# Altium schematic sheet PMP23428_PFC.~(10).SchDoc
size 431 x 279 mm; Date: Not shown in title block; ApprovedBy: Not shown in title block; CheckedBy: Not shown in title block; Author: Not shown in title block; CompanyName: Not shown in title block; Engineer: Not shown in title block; Organization: Not shown in title block; Address1: Not shown in title block; Address2: Not shown in title block; Address3: Not shown in title block; Address4: Not shown in title block; DocumentNumber: 1; Revision: Use project parameter SCH_Rev; SheetNumber: 1; SheetTotal: 3; PageSetup: Record=PageOptions¦CenterHorizontal=True¦CenterVertical=True¦PrintScale=1.00¦XCorrection=1.00¦YCorrection=1.00¦PrintKind=0¦BorderSize=5000000¦LeftOffset=0¦BottomOffset=0¦Orientation=2¦PaperLength=1000¦PaperWidth=1000¦Scale=100¦PaperSource=15¦PrintQuality=600¦MediaType=1¦DitherType=10¦PaperKind=Letter¦PrintScaleMode=1
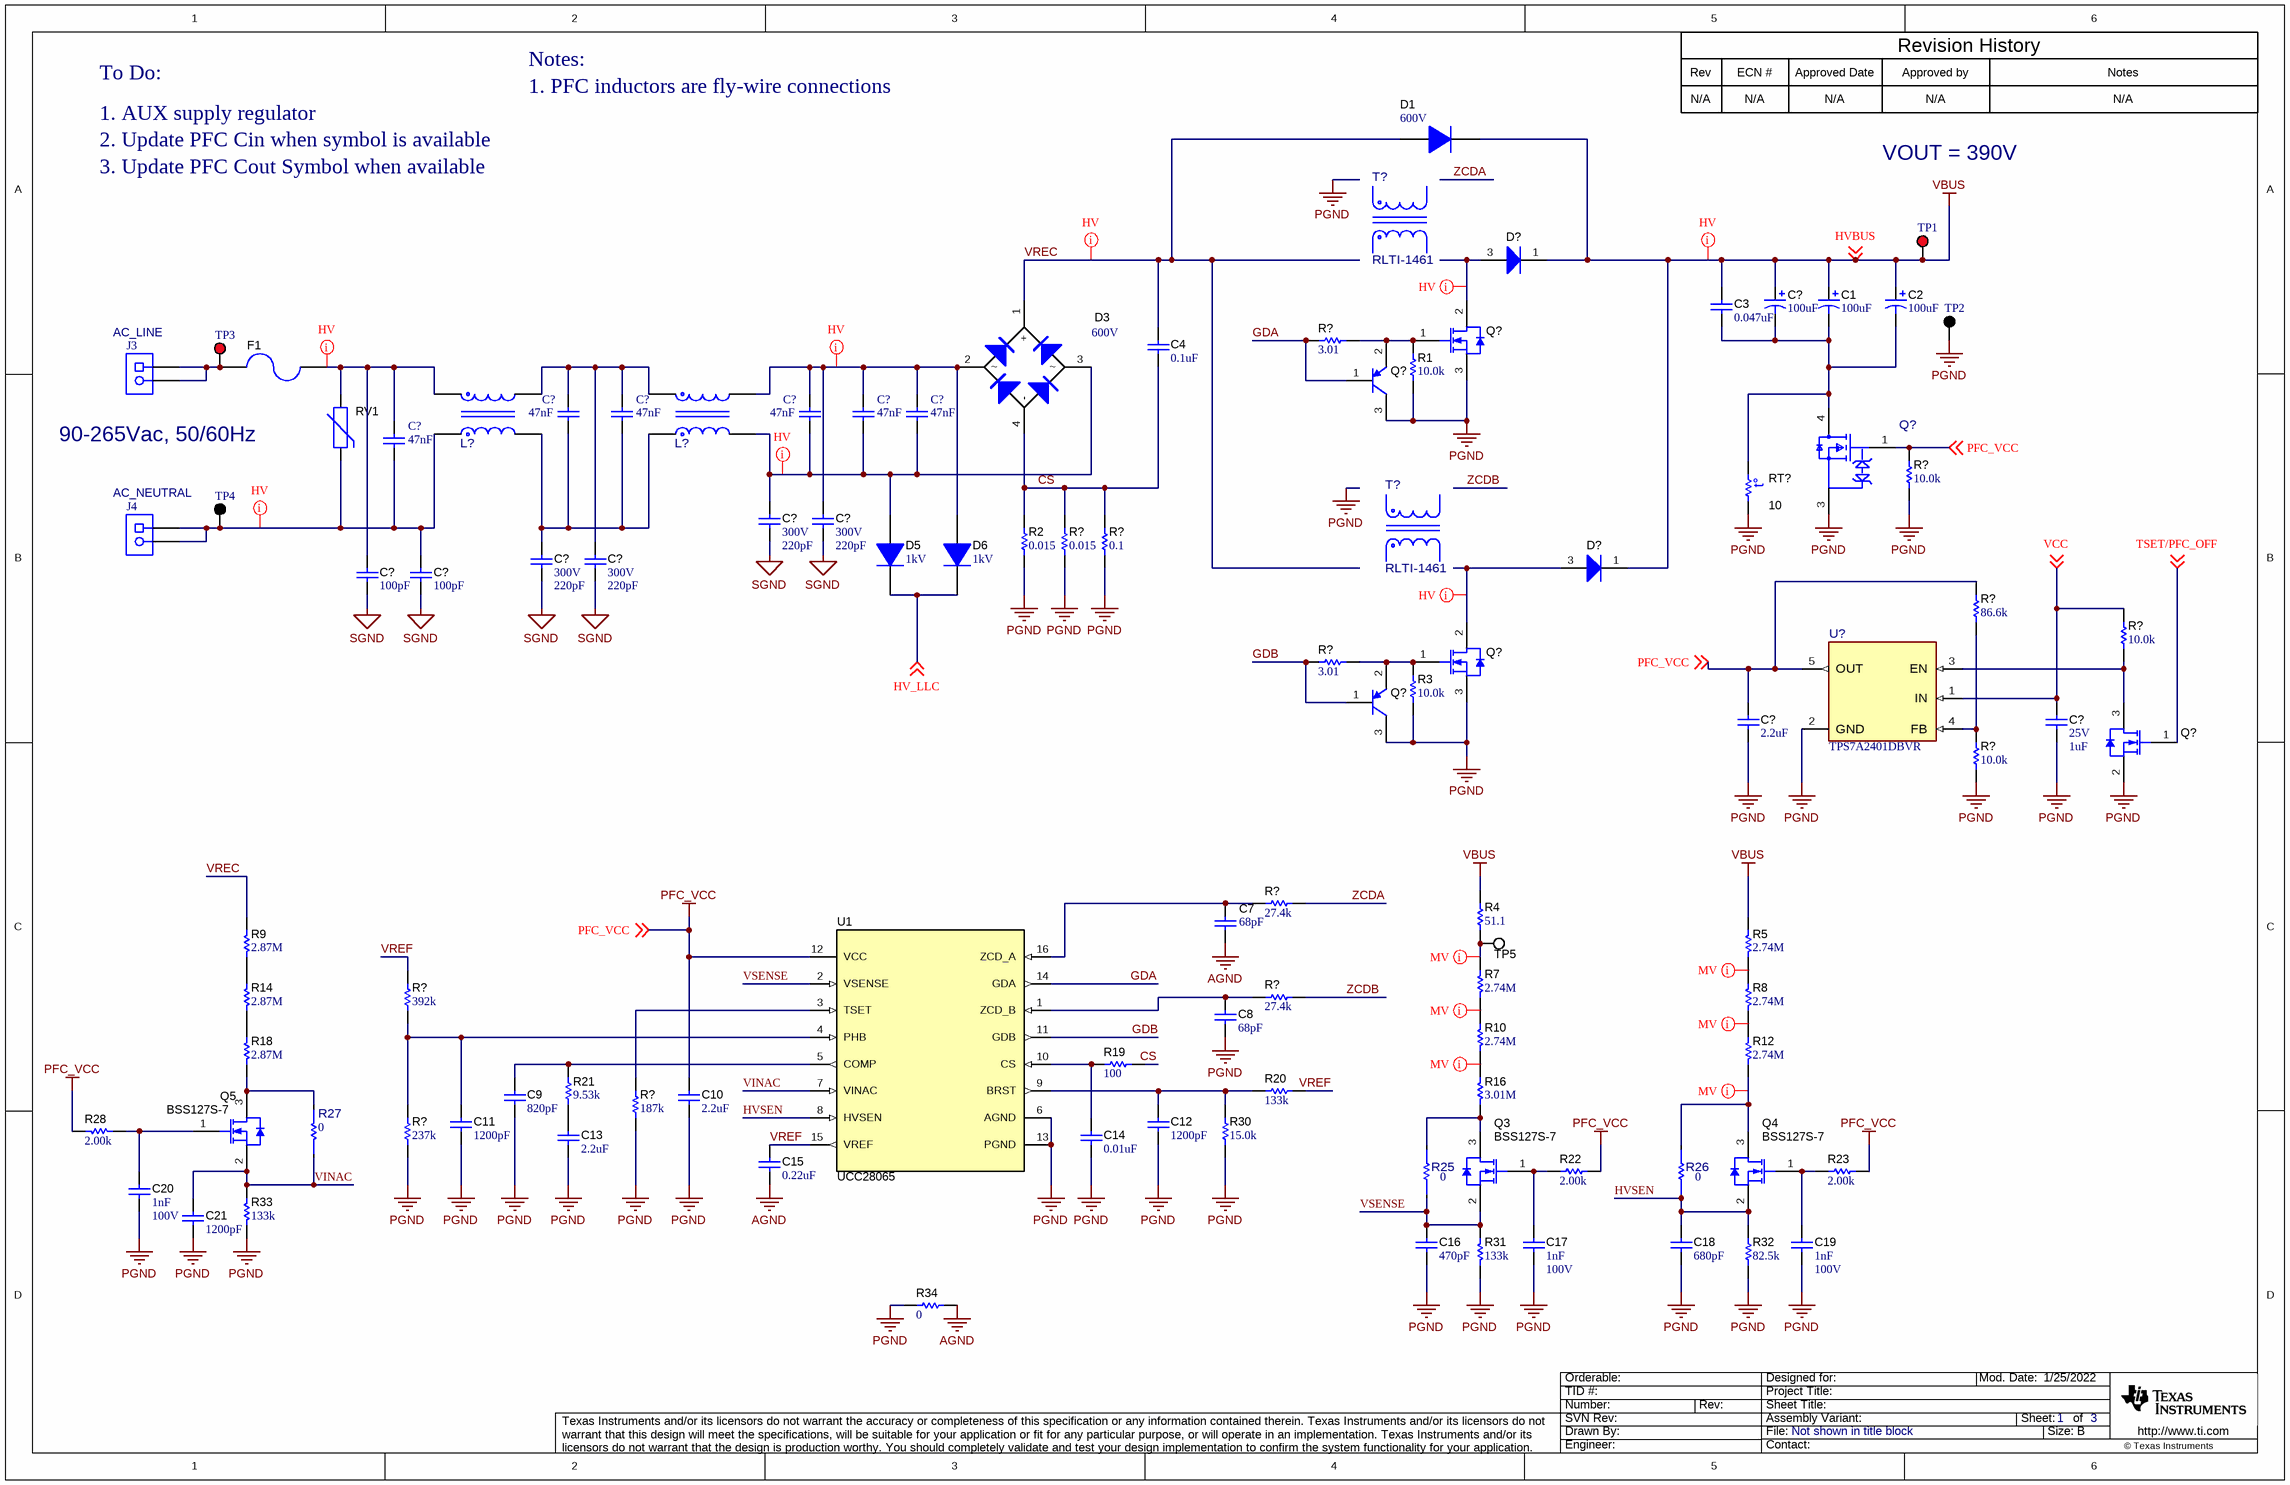
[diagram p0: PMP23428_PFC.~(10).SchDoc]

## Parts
(Parts that share a designator on the sheet are numbered #1, #2 ... from top to bottom, then left to right.)
C1  ValueDisplayed: 100uF  [KXG_1800x4000_horizontalUp]  (hidden comment: Cap_Polarized)
C2  ValueDisplayed: 100uF  [KXG_1800x4000_horizontalDown]  (hidden comment: Cap_Polarized)
C3  ValueDisplayed: 0.047uF  [ECQE_1200x1450x650]  (hidden comment: Capacitor)
C4  ValueDisplayed: 0.1uF  [CAPRR1500W60L1750T550H1250]  (hidden comment: Capacitor)
C7  ValueDisplayed: 68pF  [0805_HV]  (hidden comment: Capacitor)
C8  ValueDisplayed: 68pF  [0805_HV]  (hidden comment: Capacitor)
C9  ValueDisplayed: 820pF  [0805_HV]  (hidden comment: Capacitor)
C10  ValueDisplayed: 2.2uF  [0805_HV]  (hidden comment: Capacitor)
C11  ValueDisplayed: 1200pF  [0805_HV]  (hidden comment: Capacitor)
C12  ValueDisplayed: 1200pF  [0805_HV]  (hidden comment: Capacitor)
C13  ValueDisplayed: 2.2uF  [0805_HV]  (hidden comment: Capacitor)
C14  ValueDisplayed: 0.01uF  [0805_HV]  (hidden comment: Capacitor)
C15  ValueDisplayed: 0.22uF  [1206]  (hidden comment: Capacitor)
C16  ValueDisplayed: 470pF  [0805_HV]  (hidden comment: Capacitor)
C17  Cap_F: 1nF  VDC_V: 100V  [0603]  (hidden comment: C1608X7R2A102K080AA)
C18  ValueDisplayed: 680pF  [0805_HV]  (hidden comment: Capacitor)
C19  Cap_F: 1nF  VDC_V: 100V  [0603]  (hidden comment: C1608X7R2A102K080AA)
C20  Cap_F: 1nF  VDC_V: 100V  [0603]  (hidden comment: C1608X7R2A102K080AA)
C21  ValueDisplayed: 1200pF  [0805_HV]  (hidden comment: Capacitor)
C?#1  ValueDisplayed: 100uF  [KXG_1800x4000_horizontalUp]  (hidden comment: Cap_Polarized)
C?#2  Cap_F: 47nF  [WCAP-FTX2_L13W4.5H9.5]  (hidden comment: 890324023015)
C?#3  Cap_F: 47nF  [WCAP-FTX2_L13W4.5H9.5]  (hidden comment: 890324023015)
C?#4  Cap_F: 47nF  [WCAP-FTX2_L13W4.5H9.5]  (hidden comment: 890324023015)
C?#5  Cap_F: 47nF  [WCAP-FTX2_L13W4.5H9.5]  (hidden comment: 890324023015)
C?#6  Cap_F: 47nF  [WCAP-FTX2_L13W4.5H9.5]  (hidden comment: 890324023015)
C?#7  Cap_F: 47nF  [WCAP-FTX2_L13W4.5H9.5]  (hidden comment: 890324023015)
C?#8  VDC_V: 300V  ValueDisplayed: 220pF  [B_800x700x800]  (hidden comment: DE6B3KJ221KN3A)
C?#9  VDC_V: 300V  ValueDisplayed: 220pF  [B_800x700x800]  (hidden comment: DE6B3KJ221KN3A)
C?#10  VDC_V: 300V  ValueDisplayed: 220pF  [B_800x700x800]  (hidden comment: DE6B3KJ221KN3A)
C?#11  VDC_V: 300V  ValueDisplayed: 220pF  [B_800x700x800]  (hidden comment: DE6B3KJ221KN3A)
C?#12  ValueDisplayed: 100pF  [KY_700x500x1000]  (hidden comment: DE2B3KY101KN3AU02F)
C?#13  ValueDisplayed: 100pF  [KY_700x500x1000]  (hidden comment: DE2B3KY101KN3AU02F)
C?#14  ValueDisplayed: 2.2uF  [0805_HV]  (hidden comment: Capacitor)
C?#15  VDC_V: 25V  ValueDisplayed: 1uF  [0603]  (hidden comment: C1608X5R1E105K080AC)
D1  Vr_V: 600V  [SMC]  (hidden comment: DIODE)
D3  Vr_V: 600V  [GBU_Horizontal_Down_Standoff2300]  (hidden comment: GBU6J)
D5  Vr_V: 1kV  [DO-41]  (hidden comment: 1N4007-E3/73)
D6  Vr_V: 1kV  [DO-41]  (hidden comment: 1N4007-E3/73)
D?#1  MUR860G  [TO-220AC_HORIZ]  (value not drawn)
D?#2  MUR860G  [TO-220AC_HORIZ]  (value not drawn)
F1  0216008.MXEP  [FUSE_0216]  (value not drawn)
J3  Receptacle_2x1  [On-Shore_ED120_2DS]  (value not drawn)
J4  Receptacle_2x1  [On-Shore_ED120_2DS]  (value not drawn)
L?#1  7448680120  [FP-7448680120_PTH_CMC_27MM5_25MM0-MFG]  (value not drawn)
L?#2  7448680120  [FP-7448680120_PTH_CMC_27MM5_25MM0-MFG]  (value not drawn)
Q3  BSS127S-7  [SOT-23]
Q4  BSS127S-7  [SOT-23]
Q5  BSS127S-7  [SOT-23]
Q?#1  IPP60R099CPXKSA1  [TO-220AB_Horizontal_100mil_Standoff2300]  (value not drawn)
Q?#2  FMMT718TA  [SOT-23]  (value not drawn)
Q?#3  STB18N60DM2  [FP-STB18N60DM2_D2PAK-MFG]  (value not drawn)
Q?#4  IPP60R099CPXKSA1  [TO-220AB_Horizontal_100mil_Standoff2300]  (value not drawn)
Q?#5  FMMT718TA  [SOT-23]  (value not drawn)
Q?#6  2N7002-7-F  [SOT-23]  (value not drawn)
R1  ValueDisplayed: 10.0k  [0805_HV]  (hidden comment: Resistor)
R2  ValueDisplayed: 0.015  [2010]  (hidden comment: Resistor)
R3  ValueDisplayed: 10.0k  [0805_HV]  (hidden comment: Resistor)
R4  ValueDisplayed: 51.1  [0805_HV]  (hidden comment: Resistor)
R5  ValueDisplayed: 2.74M  [0805_HV]  (hidden comment: Resistor)
R7  ValueDisplayed: 2.74M  [0805_HV]  (hidden comment: Resistor)
R8  ValueDisplayed: 2.74M  [0805_HV]  (hidden comment: Resistor)
R9  ValueDisplayed: 2.87M  [0805_HV]  (hidden comment: Resistor)
R10  ValueDisplayed: 2.74M  [0805_HV]  (hidden comment: Resistor)
R12  ValueDisplayed: 2.74M  [0805_HV]  (hidden comment: Resistor)
R14  ValueDisplayed: 2.87M  [0805_HV]  (hidden comment: Resistor)
R16  ValueDisplayed: 3.01M  [0805_HV]  (hidden comment: Resistor)
R18  ValueDisplayed: 2.87M  [0805_HV]  (hidden comment: Resistor)
R19  ValueDisplayed: 100  [0805_HV]  (hidden comment: Resistor)
R20  ValueDisplayed: 133k  [0805_HV]  (hidden comment: CRCW0805133KFKEA)
R21  ValueDisplayed: 9.53k  [0805_HV]  (hidden comment: Resistor)
R22  ValueDisplayed: 2.00k  [0603]  (hidden comment: RC0603FR-072KL)
R23  ValueDisplayed: 2.00k  [0603]  (hidden comment: RC0603FR-072KL)
R25  value 0  [FP-RMCF1206ZT0R00_1206-MFG]  (hidden comment: RMCF1206ZT0R00)
R26  value 0  [FP-RMCF1206ZT0R00_1206-MFG]  (hidden comment: RMCF1206ZT0R00)
R27  value 0  [FP-RMCF1206ZT0R00_1206-MFG]  (hidden comment: RMCF1206ZT0R00)
R28  ValueDisplayed: 2.00k  [0603]  (hidden comment: RC0603FR-072KL)
R30  ValueDisplayed: 15.0k  [0805_HV]  (hidden comment: CRCW080515K0FKEA)
R31  ValueDisplayed: 133k  [0805_HV]  (hidden comment: Resistor)
R32  ValueDisplayed: 82.5k  [0805_HV]  (hidden comment: Resistor)
R33  ValueDisplayed: 133k  [0805_HV]  (hidden comment: CRCW0805133KFKEA)
R34  ValueDisplayed: 0  [2512]  (hidden comment: Resistor)
R?#1  ValueDisplayed: 3.01  [0603]  (hidden comment: RC0603FR-073R01L)
R?#2  ValueDisplayed: 10.0k  [0805_HV]  (hidden comment: Resistor)
R?#3  ValueDisplayed: 0.015  [2010]  (hidden comment: Resistor)
R?#4  ValueDisplayed: 0.1  [2010]  (hidden comment: CRM2010-FX-R100ELF)
R?#5  ValueDisplayed: 86.6k  [0603]  (hidden comment: RC0603FR-0786K6L)
R?#6  ValueDisplayed: 10.0k  [0603]  (hidden comment: M55342K12B10E0T)
R?#7  ValueDisplayed: 3.01  [0603]  (hidden comment: RC0603FR-073R01L)
R?#8  ValueDisplayed: 10.0k  [0603]  (hidden comment: M55342K12B10E0T)
R?#9  ValueDisplayed: 27.4k  [0603]  (hidden comment: RC0603FR-0727K4L)
R?#10  ValueDisplayed: 392k  [0603]  (hidden comment: RC0603FR-07392KL)
R?#11  ValueDisplayed: 27.4k  [0603]  (hidden comment: RC0603FR-0727K4L)
R?#12  ValueDisplayed: 187k  [0603]  (hidden comment: CRCW0603187KFKEA)
R?#13  ValueDisplayed: 237k  [0603]  (hidden comment: RC0603FR-07237KL)
RT?  value 10  [S153]  (hidden comment: B57153S0100M000)
RV1  Varistor_MetalOxide  [VAR_S10K275E2]  (value not drawn)
T?#1  RLTI-1461  [FP-RLTI-1461_PFC_IND_1IN25_3IN0-MFG]
T?#2  RLTI-1461  [FP-RLTI-1461_PFC_IND_1IN25_3IN0-MFG]
TP1  5010  [Keystone5010]  (value not drawn)
TP2  5011  [Keystone5011]  (value not drawn)
TP3  5010  [Keystone5010]  (value not drawn)
TP4  5011  [Keystone5011]  (value not drawn)
TP5  5002  [Keystone5002]  (value not drawn)
U1  UCC28065  [D0016A_N]
U?  TPS7A2401DBVR  [DBV0005A-MFG]

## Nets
AGND: C7.2 C15.2 R34.1
PFC_VCC: C10.2 C?#14.2 Q?#3.1(G) R22.2 R23.2 R28.2 R?#2.2 R?#5.1 U1.12(VCC) U?.5(OUT) ; off-sheet PFC_VCC
PGND: C8.1 C9.1 C10.1 C11.2 C12.2 C13.2 C14.2 C16.2 C17.2 C18.2 C19.2 C20.2 C21.1 C?#14.1 C?#15.2 Q?#1.3(S) Q?#2.3(C) Q?#3.3(S) Q?#4.3(S) Q?#5.3(C) Q?#6.2(S) R1.1 R2.1 R3.1 R30.1 R31.1 R32.1 R33.1 R34.2 R?#2.1 R?#3.1 R?#4.1 R?#8.1 R?#12.1 R?#13.1 RT?.1 TP2.1 U1.6(AGND) U1.13(PGND) U?.2(GND)
SGND: C?#8.2 C?#9.2 C?#10.2 C?#11.2 C?#12.2 C?#13.2
VBUS: C1.1(+) C2.1(+) C3.1 C?#1.1(+) D1.1(K) D?#1.1(K) D?#2.1(K) R4.2 R5.2 TP1.1 ; off-sheet HVBUS  [also labelled HVBUS]
CS: C4.2 D3.4(-) R2.2 R19.2 R?#3.2 R?#4.2
GDA: Q?#2.1(B) R?#1.1 U1.14(GDA)
GDB: Q?#5.1(B) R?#7.1 U1.11(GDB)
HV_LLC: D5.1(K) D6.1(K) ; off-sheet HV_LLC
HVSEN: C18.1 Q4.2(S) R26.1 R32.2 U1.8(HVSEN)
TSET/PFC_OFF: Q?#6.1(G) ; off-sheet TSET/PFC_OFF
VCC: C?#15.1 R?#6.2 U?.1(IN) ; off-sheet VCC
VINAC: C21.2 Q5.2(S) R27.1 R33.2 U1.7(VINAC)
VREC: C4.1 D1.2(A) D3.1(+) R9.1
VREF: C15.1 R20.2 R?#10.2 U1.15(VREF)
VSENSE: C16.1 Q3.2(S) R25.1 R31.2 U1.2(VSENSE)
ZCDA: R?#9.2
ZCDB: R?#11.2
NetC1_2: C1.2(-) C2.2(-) C3.2 C?#1.2(-) Q?#3.4(D) RT?.2
NetC7_1: C7.1 R?#9.1 U1.16(ZCD_A)
NetC8_2: C8.2 R?#11.1 U1.1(ZCD_B)
NetC9_2: C9.2 R21.2 U1.5(COMP)
NetC11_1: C11.1 R?#10.1 R?#13.2 U1.4(PHB)
NetC12_1: C12.1 R20.1 R30.2 U1.9(BRST)
NetC13_1: C13.1 R21.1
NetC14_1: C14.1 R19.1 U1.10(CS)
NetC17_1: C17.1 Q3.1(G) R22.1
NetC19_1: C19.1 Q4.1(G) R23.1
NetC20_1: C20.1 Q5.1(G) R28.1
NetC?#2_1: C?#2.1 C?#3.1 C?#10.1 L?#1.2 L?#2.1
NetC?#2_2: C?#2.2 C?#3.2 C?#11.1 L?#1.3 L?#2.4
NetC?#4_1: C?#4.1 C?#5.1 C?#6.1 C?#8.1 D3.3 D5.2(A) L?#2.2
NetC?#4_2: C?#4.2 C?#5.2 C?#6.2 C?#9.1 D3.2 D6.2(A) L?#2.3
NetC?#7_1: C?#7.1 C?#13.1 J4.1 J4.2 L?#1.1 RV1.2 TP4.1
NetC?#7_2: C?#7.2 C?#12.1 F1.1 L?#1.4 RV1.1
NetD?#1_3: D?#1.3(A) Q?#1.2(D)
NetD?#2_3: D?#2.3(A) Q?#4.2(D)
NetF1_2: F1.2 J3.1 J3.2 TP3.1
NetQ3_3: Q3.3(D) R16.2 R25.2
NetQ4_3: Q4.3(D) R12.1 R26.2
NetQ5_3: Q5.3(D) R18.1 R27.2
NetQ?#1_1: Q?#1.1(G) Q?#2.2(E) R1.2 R?#1.2
NetQ?#4_1: Q?#4.1(G) Q?#5.2(E) R3.2 R?#7.2
NetQ?#6_3: Q?#6.3(D) R?#6.1 U?.3(EN)
NetR4_1: R4.1 R7.1 TP5.1
NetR5_1: R5.1 R8.2
NetR7_2: R7.2 R10.1
NetR8_1: R8.1 R12.2
NetR9_2: R9.2 R14.1
NetR10_2: R10.2 R16.1
NetR14_2: R14.2 R18.2
NetR?#5_2: R?#5.2 R?#8.2 U?.4(FB)
NetR?#12_2: R?#12.2 U1.3(TSET)

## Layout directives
net class HV: NetC?#4_1, NetC?#4_2, NetC?#7_1, NetC?#7_2, NetD?#1_3, NetD?#2_3, VBUS, VREC
net class MV: NetQ4_3, NetR4_1, NetR5_1, NetR7_2, NetR8_1, NetR10_2

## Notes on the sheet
- To Do:
- Notes:
- 1. PFC inductors are fly-wire connections
- Rev
- N/A
- ECN #
- Approved Date
- Approved by
- Revision History
- Notes
- 1. AUX supply regulator
- 2. Update PFC Cin when symbol is available
- VOUT = 390V
- 3. Update PFC Cout Symbol when available
- (near J3) AC_LINE
- 90-265Vac, 50/60Hz
- (near J4) AC_NEUTRAL

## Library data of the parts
C1 C2 C?#1 = CMP-0010042-2: CAP, AL, 100 uF, 450 V, +/- 20%, TH; PartNumber: EKXG451ELL101MM40S; Manufacturer: Chemi-Con; Polarized: Y; CompType: Capacitor; Value: 100uF; U/M: EA; Cap_F: 100µF; Value1: Unknown; VDC_V: 450V; IRMS_A: 8dA; TaMin_C: -25°C; TaMax_C: 105°C; Cap_Case: 18x40mm; SizeAreaWB_mm2: 400; SizeArea_mm2: 324; SizeX_mm: 18; SizeZ_mm: 41.5; AEC Category: Q200; AEC Qualified: N
C3 = CMP-0012494-3: CAP, Film, 0.047 uF, 630 V, +/- 10%, TH; PartNumber: ECQ-E6473KF; Manufacturer: Panasonic; Polarized: N; Cap_F: 47nF; Value1: Unknown; VDC_V: 630V; TaMin_C: -40°C; TaMax_C: 105°C; Cap_Case: 12x14.5x6.5mm; SizeAreaWB_mm2: 119; SizeArea_mm2: 78; SizeX_mm: 12; SizeY_mm: 6.5; SizeZ_mm: 14.5; AEC Category: Q200
C4 = CMP-0012496-3: CAP, Film, 0.1 uF, 275 V, +/- 20%, TH; PartNumber: ECQ-U2A104ML; Manufacturer: Panasonic; Polarized: N; Value: 0.1uF; Cap_F: 100nF; Value1: Unknown; VDC_V: 275V; TaMin_C: -40°C; TaMax_C: 100°C; Cap_Case: Radial 17.5x5.5x12.5; AEC Category: Q200
C7 C8 = CMP-0007622-2: CAP, CERM, 68 pF, 50 V, +/- 5%, C0G/NP0, 0805; PartNumber: 08055A680JAT2A; Manufacturer: AVX; Polarized: N; Value: 68pF; U/M: EA; ESR_ohm: 4.5d; Value1: 0.45 ohm; VDC_V: 50V; TaMin_C: -55°C; TaMax_C: 125°C; Cap_Case: 0805; SizeArea_mm2: 2.5; SizeAreaWB_mm2: 6.75; SizeX_mm: 2; SizeY_mm: 1.25; SizeZ_mm: 1.45; AEC Category: Q200
C9 = CMP-0008153-2: CAP, CERM, 820 pF, 25 V, +/- 10%, X7R, 0805; PartNumber: GRM216R71E821KA01D; Manufacturer: MuRata; Polarized: N; Value: 820pF; U/M: EA; Value1: Unknown; VDC_V: 25V; TaMin_C: -55°C; TaMax_C: 125°C; Cap_Case: 0805; SizeArea_mm2: 2.5; SizeAreaWB_mm2: 6.75; SizeX_mm: 2; SizeY_mm: 1.25; SizeZ_mm: 1.45; AEC Category: Q200
C10 C13 C?#14 = CMP-0007877-2: CAP, CERM, 2.2 uF, 50 V, +/- 10%, X7R, 0805; PartNumber: C2012X7R1H225K125AC; Manufacturer: TDK; Polarized: N; Value: 2.2uF; U/M: EA; Cap_F: 2.2µF; ESR_ohm: 3.66m; Value1: 0.00366 ohm; VDC_V: 50V; IRMS_A: 3.41207A; TaMin_C: -55°C; TaMax_C: 125°C; Cap_Case: 0805; SizeArea_mm2: 2.5; SizeAreaWB_mm2: 6.75; SizeX_mm: 2; SizeY_mm: 1.25; SizeZ_mm: 1.45; AEC Category: Q200
C11 C12 C21 = CMP-0008142-2: CAP, CERM, 1200 pF, 25 V, +/- 10%, X7R, 0805; PartNumber: GRM216R71E122KA01D; Manufacturer: MuRata; Polarized: N; Value: 1200pF; U/M: EA; Cap_F: 1.2nF; Value1: Unknown; VDC_V: 25V; TaMin_C: -55°C; TaMax_C: 125°C; Cap_Case: 0805; SizeArea_mm2: 2.5; SizeAreaWB_mm2: 6.75; SizeX_mm: 2; SizeY_mm: 1.25; SizeZ_mm: 1.45; AEC Category: Q200
C14 = CMP-0007629-2: CAP, CERM, 0.01 uF, 50 V, +/- 5%, X7R, 0805; PartNumber: 08055C103JAT2A; Manufacturer: AVX; Polarized: N; Value: 0.01uF; U/M: EA; Cap_F: 10nF; ESR_ohm: 0.078; Value1: 0.078 ohm; VDC_V: 50V; TaMin_C: -55°C; TaMax_C: 125°C; Cap_Case: 0805; SizeArea_mm2: 2.5; SizeAreaWB_mm2: 6.75; SizeX_mm: 2; SizeY_mm: 1.25; SizeZ_mm: 1.45; AEC Category: Q200
C15 = CMP-0008995-2: CAP, CERM, 0.22 uF, 50 V, +/- 10%, X7R, 1206; PartNumber: GRM31MR71H224KA01L; Manufacturer: MuRata; Polarized: N; Value: 0.22uF; U/M: EA; Cap_F: 220nF; Value1: Unknown; VDC_V: 50V; TaMin_C: -55°C; TaMax_C: 125°C; SizeArea_mm2: 5.12; SizeAreaWB_mm2: 10.92; SizeX_mm: 3.2; SizeY_mm: 1.6; SizeZ_mm: 1.35; AEC Category: Q200
C16 = CMP-0008150-2: CAP, CERM, 470 pF, 25 V, +/- 10%, X7R, 0805; PartNumber: GRM216R71E471KA01D; Manufacturer: MuRata; Polarized: N; Value: 470pF; U/M: EA; Value1: Unknown; VDC_V: 25V; TaMin_C: -55°C; TaMax_C: 125°C; Cap_Case: 0805; SizeArea_mm2: 2.5; SizeAreaWB_mm2: 6.75; SizeX_mm: 2; SizeY_mm: 1.25; SizeZ_mm: 1.45; AEC Category: Q200
C17 C19 C20 = CMP-0007053-4: CAP, CERM, 1000 pF, 100 V, +/- 10%, X7R, 0603; Manufacturer: TDK; TaMin_C: -55°C; Polarized: N; SizeAreaWB_mm2: 4.68; Value1: Unknown; U/M: EA; Value: 1000pF; TaMax_C: 125°C; SizeZ_mm: 1; SizeX_mm: 1.6; SizeY_mm: 0.8; SizeArea_mm2: 1.28; AEC Category: Q200
C18 = CMP-0007693-2: CAP, CERM, 680 pF, 25 V, +/- 10%, X7R, 0805; PartNumber: 885012207059; Manufacturer: Wurth Elektronik; Polarized: N; Value: 680pF; U/M: EA; Value1: Unknown; VDC_V: 25V; TaMin_C: -55°C; TaMax_C: 125°C; Cap_Case: 0805; SizeArea_mm2: 2.5; SizeAreaWB_mm2: 6.75; SizeX_mm: 2; SizeY_mm: 1.25; SizeZ_mm: 1.45; AEC Category: Q200
C?#2-C?#7 = CMP-0112456-1: WCAP-FTX2 Film Capacitor, THT, L13 x W4.5 x H9.5mm, 47nF, 275V; Manufacturer: Wurth Elektronik; Capacitance Tolerance: +/-10%; Dissipation Factor @100kHz: 0.5%; Dissipation Factor @10kHz: 0.1%; Insulation Resistance: 30000MOhm; Pitch: 10mm; Rate of Voltage Rise: 300V/us; Technical Reference: MX2P010473K275ASPB15000
C?#8-C?#11 = CMP-0009612-2: CAP, CERM, 220 pF, 300 V, +/- 10%, B, TH, 2- Leads, Body 8x7mm, Pin Spacing 7.5mm; Manufacturer: MuRata; TaMin_C: -40°C; Polarized: N; SizeAreaWB_mm2: 90; Value1: Unknown; U/M: EA; Value: 220pF; TaMax_C: 125°C; SizeZ_mm: 11; SizeX_mm: 8; SizeY_mm: 7; Cap_Case: 8x7x8mm; SizeArea_mm2: 56; AEC Category: Q200
C?#12 C?#13 = CMP-0009606-4: CAP, CERM, 100 pF, X1 250 VAC/Y2 300 VAC, +/- 10%, B, TH; Manufacturer: MuRata; TaMin_C: -25°C; Polarized: N; SizeAreaWB_mm2: 66.5; Value1: Unknown; U/M: EA; Value: 100pF; TaMax_C: 85°C; SizeZ_mm: 10; SizeX_mm: 7.5; SizeY_mm: 5; Cap_Case: 7x5x10mm; SizeArea_mm2: 37.5; AEC Category: Q200; AC_Safety: X1Y2; VAC_X: 250V; VAC_Y: 300V
C?#15 = CMP-0007006-5: CAP, CERM, 1 uF, 25 V, +/- 10%, X5R, 0603; Manufacturer: TDK; TaMin_C: -55°C; Polarized: N; SizeAreaWB_mm2: 4.68; Value1: Unknown; U/M: EA; Value: 1uF; TaMax_C: 85°C; SizeZ_mm: 1; SizeX_mm: 1.6; SizeY_mm: 0.8; SizeArea_mm2: 1.28; Cap_F: 1µF; AEC Category: Q200
D1 = CMP-0076905-1: Diode, Ultrafast, 600 V, 3 A, SMC; PartNumber: MURS360T3G; Manufacturer: ON Semiconductor; U/M: EA; Vf_V: 1.25V; Value: 600V; Value1: 3A; TJmax_C: 175°C; RJC_CperW: 11.0; SizeAreaWB_mm2: 83.2686; SizeArea_mm2: 50.5686; SizeX_mm: 8.13; SizeY_mm: 6.22; SizeZ_mm: 2.6; AEC Category: Q101; Green_Lifecycle: Active; Green_REACh: Passed
D3 = CMP-0029269-2: Diode, Switching-Bridge, 600 V, 6 A, TH; Manufacturer: Fairchild Semiconductor; U/M: EA; Vf_V: 1V; Value: 600V; Value1: 6A; TJmax_C: 150°C; RJC_CperW: 3.1; SizeAreaWB_mm2: 130.5915; SizeArea_mm2: 75.6315; SizeX_mm: 22.05; SizeY_mm: 3.43; SizeZ_mm: 21.55; AEC Category: Q101; AEC Qualified: N; Green_Lifecycle: Active; Green_REACh: Passed
D5 D6 = CMP-0029188-2: Diode, P-N, 1000 V, 1 A, TH; Manufacturer: Vishay-Semiconductor; Io_A: 1A; SizeAreaWB_mm2: 43.424; TJmax_C: 150°C; Value: 1000V; SizeZ_mm: 23.4; SizeX_mm: 7.2; SizeY_mm: 2.72; Vf_V: 1.1V; SizeArea_mm2: 19.584; AEC Qualified: N; AEC Category: Q101
D?#1 D?#2 = CMP-0029037-2: Diode, Ultrafast, 600 V, 8 A, TH; Manufacturer: ON Semiconductor; TJmax_C: 175°C; Green_Lifecycle: Not Set; SizeX_mm: 10.15; SizeAreaWB_mm2: 78.975; RJC_CperW: 4.75; SizeArea_mm2: 45.675; Green_REACh: Incomplete; Vf_V: 980mV; Value2: 0.98V; Io_A: 8A; SizeY_mm: 4.5; AEC Category: Q101; SizeZ_mm: 23; Value: 600V
F1 = CMP-0079917-1: Fuse, 8 A, 250 VAC, TH; Manufacturer: Littelfuse; VAC_V: 250V; Rtyp_Ohm: 0.0123; MeltingTyp: 64.315; Irating_A: 8A; Interrupt_AC: 1.5kA
J3 J4 = CMP-0074910-1: Terminal Block, 5.08 mm, 2x1, Brass, TH; PartNumber: ED120/2DS; Manufacturer: On-Shore Technology; Pitch_mm: 5.08; Gender: Female; Shrouded: N; Row_Count: 1; Current_A: 15A; Voltage_V: 300V; Cert_CULUS: Y; Green_Lifecycle: Not Set; Green_REACh: Incomplete; CNHeader: False; CT: True
L?#1 L?#2 = CMP-0120034-1: 330 µH @ 10 kHz 2 Line Common Mode Choke Through Hole 12A DCR 6mOhm; Manufacturer: Wurth Electronics; DCR_ohm: 6m; Ind_H: 330µH; SizeZ_mm: 10mm; AEC Qualified: No; TaMax_C: +60°C; TaMin_C: -40°C; Test Frequency: 10kHz; Tolerance_%: 40%
Q3-Q5 = CMP-0001149-3: MOSFET, N-CH, 600 V, 0.05 A, SOT-23; Alternate Manufacturer: None; Manufacturer: Diodes Inc.; SizeZ_mm: 1.1; ChType: N; Value2: 1.08 nC; VdsMax_V: 600V; SizeX_mm: 2.5; SizeY_mm: 3; Vgs_V: 20V; QgTyp_nC: 1.08; Value: 600V; SizeArea_mm2: 7.5; AEC Category: Q101; IdsMax_A: 50mA; SizeAreaWB_mm2: 14; U/M: EA
Q?#1 Q?#4 = CMP-0001172-3: MOSFET, N-CH, 600 V, 31 A, TO-220AB; Alternate Manufacturer: None; Manufacturer: Infineon Technologies; SizeZ_mm: 19.4; ChType: N; Value2: 60 nC; VdsMax_V: 600V; SizeX_mm: 10.2; SizeY_mm: 4.5; Vgs_V: 20V; Value: 600V; SizeArea_mm2: 45.9; AEC Category: Q101; IdsMax_A: 31A; SizeAreaWB_mm2: 79.3; U/M: EA; QgTyp_nC: 60
Q?#2 Q?#5 = CMP-0000330-2: Transistor, PNP, 20 V, 1.5 A, SOT-23; Manufacturer: Diodes Inc.; TaMax_C: 150°C; Value2: 6; Value1: 1.5 A; Vcesat1_V: 20V; SizeX_mm: 2.5; SizeY_mm: 3; TaMin_C: -55°C; IcRated_A: 1.5A; CompType: BJT; SizeZ_mm: 1.1; Value: 20 V; SizeArea_mm2: 7.5; NPN: 0; PNP: 1; AEC Category: Q101; SizeAreaWB_mm2: 14; U/M: EA
Q?#3 = CMP-0084087-1: N-Channel 600V 12A (Tc) 90W (Tc) Surface Mount D2PAK; Manufacturer: STMicroelectronics; Rdson45_ohm: 0.26Ω; Threshold Vgs Max: 5V; Input Capacitace At Vds: 800pF @ 100V; Turn On Delay Time: 13.5ns; AEC Qualified: No; ChMode: False; Symbol Name: SYM-STB18N60DM2; Max Forward Diode Voltage: 1.6V; Vgs_V: 25V; Pulse Drain Current: 48A; Standoff Height: 0.03mm; Reverse Recovery Time: 125ns; Number Of N Channels: 1; Turn Off Delay Time: 9.5ns; QgTyp_nC: 20nC @ 10V; TJmax_C: +150°C; Reverse Recovery Charge: 675nC; Power_W: 110W; SizeZ_mm: 4.83mm; Threshold Vgs Min: 3V
Q?#6 = CMP-0000769-1: MOSFET, N-CH, 60 V, 0.17 A, SOT-23; Alternate Manufacturer: None; Manufacturer: Diodes Inc.; SizeZ_mm: 1.1; ChType: N; Value2: 223 nC; Value1: 7; VdsMax_V: 60V; SizeX_mm: 2.5; SizeY_mm: 3; Vgs_V: 20V; Value: 60V; Rdson45_ohm: 7.5; AEC Category: Q101; IdsMax_A: 1.7dA; SizeAreaWB_mm2: 14; U/M: EA; QgTyp_nC: 223
R1 R3 R?#2 = CMP-0020842-3: RES, 10.0 k, 1%, 0.125 W, AEC-Q200 Grade 0, 0805; PartNumber: CRCW080510K0FKEA; Manufacturer: Vishay-Dale; Value: 10.0k; Res_ohm: 10k; Value_Code: 10k0; Power_W: 125mW; Value2: 0.125W; VDC_V: 150V; TempCo: 100 ppm/C; SizeArea_mm2: 2.5; SizeX_mm: 2; SizeY_mm: 1.25; SizeZ_mm: 1.45; EIA_Code: E96; AEC Category: Q200; AEC Qualified: Y; AEC Grade: 0
R2 R?#3 = CMP-0016558-2: RES, 0.015, 1%, 0.5 W, 2010; PartNumber: WSL2010R0150FEA; Manufacturer: Vishay-Dale; Value: 0.015; Value_Code: R015; Power_W: 500mW; Value2: 0.5W; TempCo: 75 ppm/C; SizeArea_mm2: 12.5; SizeX_mm: 5; SizeY_mm: 2.5; SizeZ_mm: 1.66; EIA_Code: E96; U/M: EA; AEC Category: Q200
R4 = CMP-0020156-2: RES, 51.1, 0.1%, 0.125 W, 0805; PartNumber: RT0805BRD0751R1L; Manufacturer: Yageo America; Value: 51.1; Value_Code: 51R1; Power_W: 125mW; Value2: 0.125W; VDC_V: 150V; TempCo: 25 ppm/C; SizeArea_mm2: 2.5; SizeX_mm: 2; SizeY_mm: 1.25; SizeZ_mm: 1.45; EIA_Code: E192; U/M: EA; AEC Category: Q200
R5 R7 R8 R10 R12 = CMP-0021137-3: RES, 2.74 M, 1%, 0.125 W, AEC-Q200 Grade 0, 0805; PartNumber: CRCW08052M74FKEA; Manufacturer: Vishay-Dale; Value: 2.74Meg; Value_Code: 2M74; Power_W: 125mW; Value2: 0.125W; VDC_V: 150V; TempCo: 100 ppm/C; SizeArea_mm2: 2.5; SizeX_mm: 2; SizeY_mm: 1.25; SizeZ_mm: 1.45; EIA_Code: E96; AEC Category: Q200; AEC Qualified: Y; AEC Grade: 0
R9 R14 R18 = CMP-0021139-3: RES, 2.87 M, 1%, 0.125 W, AEC-Q200 Grade 0, 0805; PartNumber: CRCW08052M87FKEA; Manufacturer: Vishay-Dale; Value: 2.87Meg; Value_Code: 2M87; Power_W: 125mW; Value2: 0.125W; VDC_V: 150V; TempCo: 100 ppm/C; SizeArea_mm2: 2.5; SizeX_mm: 2; SizeY_mm: 1.25; SizeZ_mm: 1.45; EIA_Code: E96; AEC Category: Q200; AEC Qualified: Y; AEC Grade: 0
R16 = CMP-0021219-4: RES, 3.01 M, 1%, 0.125 W, AEC-Q200 Grade 0, 0805; PartNumber: CRCW08053M01FKEA; Manufacturer: Vishay-Dale; Value: 3.01Meg; Value_Code: 3M01; Power_W: 125mW; Value2: 0.125W; VDC_V: 150V; TempCo: 100 ppm/C; SizeArea_mm2: 2.5; SizeX_mm: 2; SizeY_mm: 1.25; SizeZ_mm: 1.45; EIA_Code: E96; AEC Category: Q200; AEC Qualified: Y; AEC Grade: 0
R19 = CMP-0020835-3: RES, 100, 1%, 0.125 W, AEC-Q200 Grade 0, 0805; PartNumber: CRCW0805100RFKEA; Manufacturer: Vishay-Dale; Value: 100; Value_Code: 100R; Power_W: 125mW; Value2: 0.125W; VDC_V: 150V; TempCo: 100 ppm/C; SizeArea_mm2: 2.5; SizeX_mm: 2; SizeY_mm: 1.25; SizeZ_mm: 1.45; EIA_Code: E96; AEC Category: Q200; AEC Qualified: Y; AEC Grade: 0
R20 R33 = CMP-0020881-3: RES, 133 k, 1%, 0.125 W, AEC-Q200 Grade 0, 0805; Manufacturer: Vishay-Dale; Power_W: 125mW; TempCo: 100 ppm/C; Value: 133k; EIA_Code: E96; SizeX_mm: 2; SizeY_mm: 1.25; SizeZ_mm: 1.45; Value2: 0.125W; SizeArea_mm2: 2.5; AEC Qualified: Y; VDC_V: 150V; AEC Category: Q200; AEC Grade: 0
R21 = CMP-0021817-2: RES, 9.53 k, 1%, 0.125 W, 0805; PartNumber: ERJ-6ENF9531V; Manufacturer: Panasonic; Value: 9.53k; Value_Code: 9k53; Power_W: 125mW; Value2: 0.125W; TempCo: 100 ppm/C; SizeArea_mm2: 2.5; SizeX_mm: 2; SizeY_mm: 1.25; SizeZ_mm: 1.45; EIA_Code: E96; U/M: EA; AEC Category: Q200
R22 R23 R28 = CMP-0023000-5: RES, 2.00 k, 1%, 0.1 W, 0603; Manufacturer: Yageo; Power_W: 100mW; TempCo: 100 ppm/C; Value_Code: 2k00; Value: 2.00k; EIA_Code: E96; Res_ohm: 2k; SizeX_mm: 1.6; SizeY_mm: 0.8; SizeZ_mm: 1; Value2: 0.1W; SizeArea_mm2: 1.28; AEC Qualified: N; VDC_V: 75V; AEC Category: Q200; SizeAreaWB_mm2: 4.68
R25-R27 = CMP-0093609-1: 0Ω ±0 0.25W 1206 Thick Film Chip Resistor AEC-Q200 compliant; Manufacturer: Stackpole Electronics; AEC Qualified: Yes; VDC_V: 200V; AEC Grade: Grade 0; Power_W: 250mW; SizeZ_mm: 0.7mm
R30 = CMP-0020909-3: RES, 15.0 k, 1%, 0.125 W, AEC-Q200 Grade 0, 0805; Manufacturer: Vishay-Dale; Power_W: 125mW; TempCo: 100 ppm/C; Value_Code: 15k0; Value: 15.0k; EIA_Code: E96; Res_ohm: 15k; SizeX_mm: 2; SizeY_mm: 1.25; SizeZ_mm: 1.45; Value2: 0.125W; SizeArea_mm2: 2.5; AEC Qualified: Y; VDC_V: 150V; AEC Category: Q200; AEC Grade: 0
R31 = CMP-0020881-3: RES, 133 k, 1%, 0.125 W, AEC-Q200 Grade 0, 0805; PartNumber: CRCW0805133KFKEA; Manufacturer: Vishay-Dale; Value: 133k; Power_W: 125mW; Value2: 0.125W; VDC_V: 150V; TempCo: 100 ppm/C; SizeArea_mm2: 2.5; SizeX_mm: 2; SizeY_mm: 1.25; SizeZ_mm: 1.45; EIA_Code: E96; AEC Category: Q200; AEC Qualified: Y; AEC Grade: 0
R32 = CMP-0021455-3: RES, 82.5 k, 1%, 0.125 W, AEC-Q200 Grade 0, 0805; PartNumber: CRCW080582K5FKEA; Manufacturer: Vishay-Dale; Value: 82.5k; Value_Code: 82k5; Power_W: 125mW; Value2: 0.125W; VDC_V: 150V; TempCo: 100 ppm/C; SizeArea_mm2: 2.5; SizeX_mm: 2; SizeY_mm: 1.25; SizeZ_mm: 1.45; EIA_Code: E96; AEC Category: Q200; AEC Qualified: Y; AEC Grade: 0
R34 = CMP-0015864-3: RES, 0, 5%, 1 W, AEC-Q200 Grade 0, 2512; PartNumber: CRCW25120000Z0EG; Manufacturer: Vishay-Dale; Value: 0; Value_Code: 0000; Power_W: 1W; TempCo: ppm/C; SizeArea_mm2: 20.16; SizeX_mm: 6.3; SizeY_mm: 3.2; SizeZ_mm: 0.71; EIA_Code: E24; AEC Category: Q200; AEC Qualified: Y
R?#1 R?#7 = CMP-0023093-5: RES, 3.01, 1%, 0.1 W, 0603; Manufacturer: Yageo; Power_W: 100mW; TempCo: 200 ppm/C; Value_Code: 3R01; Value: 3.01; EIA_Code: E96; SizeX_mm: 1.6; SizeY_mm: 0.8; SizeZ_mm: 1; Value2: 0.1W; SizeArea_mm2: 1.28; AEC Qualified: N; VDC_V: 75V; AEC Category: Q200; SizeAreaWB_mm2: 4.68
R?#4 = CMP-0016505-2: RES, 0.1, 1%, 1 W, 2010; Manufacturer: Bourns; Power_W: 1W; TempCo: 150 ppm/C; Value_Code: R100; U/M: EA; Value: 0.1; EIA_Code: E96; Res_ohm: 1d; SizeX_mm: 5; SizeY_mm: 2.5; SizeZ_mm: 1.66; SizeArea_mm2: 12.5; VDC_V: 0V; AEC Category: Q200
R?#5 = CMP-0023301-5: RES, 86.6 k, 1%, 0.1 W, 0603; Manufacturer: Yageo; Power_W: 100mW; TempCo: 100 ppm/C; Value_Code: 86k6; Value: 86.6k; EIA_Code: E96; SizeX_mm: 1.6; SizeY_mm: 0.8; SizeZ_mm: 1; Value2: 0.1W; SizeArea_mm2: 1.28; AEC Qualified: N; VDC_V: 75V; AEC Category: Q200; SizeAreaWB_mm2: 4.68
R?#6 R?#8 = CMP-0080488-1: RES, 10.0 k, 1%, 0.1 W, 0603; Manufacturer: TT Electronics/IRC; Power_W: 100mW; TempCo: 100 ppm/C; SizeAreaWB_mm2: 4.68; Value_Code: 10k0; Value: 10.0k; EIA_Code: E96; Res_ohm: 10k; SizeX_mm: 1.6; SizeY_mm: 0.8; SizeZ_mm: 1; Value2: 0.1W; SizeArea_mm2: 1.28; AEC Qualified: N; AEC Category: Q200
R?#9 R?#11 = CMP-0022965-5: RES, 27.4 k, 1%, 0.1 W, 0603; Manufacturer: Yageo; Power_W: 100mW; TempCo: 100 ppm/C; Value_Code: 27k4; Value: 27.4k; EIA_Code: E96; SizeX_mm: 1.6; SizeY_mm: 0.8; SizeZ_mm: 1; Value2: 0.1W; SizeArea_mm2: 1.28; AEC Qualified: N; VDC_V: 75V; AEC Category: Q200; SizeAreaWB_mm2: 4.68
R?#10 = CMP-0023070-4: RES, 392 k, 1%, 0.1 W, 0603; Manufacturer: Yageo; Power_W: 100mW; TempCo: 100 ppm/C; Value: 392k; EIA_Code: E96; SizeX_mm: 1.6; SizeY_mm: 0.8; SizeZ_mm: 1; Value2: 0.1W; SizeArea_mm2: 1.28; AEC Qualified: N; VDC_V: 75V; AEC Category: Q200; SizeAreaWB_mm2: 4.68
R?#12 = CMP-0022095-4: RES, 187 k, 1%, 0.1 W, AEC-Q200 Grade 0, 0603; Manufacturer: Vishay-Dale; Power_W: 100mW; TempCo: 100 ppm/C; Value: 187k; EIA_Code: E96; SizeX_mm: 1.6; SizeY_mm: 0.8; SizeZ_mm: 1; Value2: 0.1W; SizeArea_mm2: 1.28; AEC Qualified: Y; VDC_V: 75V; AEC Category: Q200; AEC Grade: 0
R?#13 = CMP-0022931-4: RES, 237 k, 1%, 0.1 W, 0603; Manufacturer: Yageo; Power_W: 100mW; TempCo: 100 ppm/C; Value: 237k; EIA_Code: E96; SizeX_mm: 1.6; SizeY_mm: 0.8; SizeZ_mm: 1; Value2: 0.1W; SizeArea_mm2: 1.28; AEC Qualified: N; VDC_V: 75V; AEC Category: Q200; SizeAreaWB_mm2: 4.68
RT? = CMP-0002550-2: Thermistor NTC, 10 ohm, 20%, 8.5mm Disc; Manufacturer: TDK; TaMax_C: 175°C; TaMin_C: -55°C; Power_W: 1.4W; U/M: EA
RV1 = CMP-0002100-2: Varistor 275V RMS 10MM Radial, TH; PartNumber: S10K275E2; Manufacturer: TDK; SizeAreaWB_mm2: 103.6; SizeArea_mm2: 64.8; SizeX_mm: 12; SizeY_mm: 5.4; SizeZ_mm: 14.5
T?#1 T?#2 = CMP-0120250-1: PFCINDUCTOR PMP23428 683W; Manufacturer: Renco Electronics; DCR_ohm: 18m; Ind_H: 85µH; Ns1toNp: 1:0.2; SizeZ_mm: 0.39inch; AEC Qualified: No
TP1 TP3 = CMP-0055147-2: Test Point, Multipurpose, Red, TH; Manufacturer: Keystone Electronics; CT: TRUE; ContactFinish: Silver; Green_Lifecycle: Active; CNHeader: FALSE; Green_REACh: Passed
TP2 TP4 = CMP-0055148-2: Test Point, Multipurpose, Black, TH; Manufacturer: Keystone Electronics; CNHeader: FALSE; ContactFinish: Silver; Green_REACh: Passed; Green_Lifecycle: Active; CT: TRUE
TP5 = CMP-0055139-1: Test Point, Miniature, White, TH; Manufacturer: Keystone; CNHeader: FALSE; Green_Lifecycle: Active; Green_REACh: Passed; ContactFinish: Silver; CT: TRUE
U1 = CMP-0065070-4: Manufacturer: Texas Instruments; SizeX_mm: 6.0; SizeY_mm: 9.9; CompType: IC; SizeZ_mm: 1.75; SizeArea_mm2: 59.4; SizeAreaWB_mm2: 95.2; U/M: EA
U? = CMP-0089843-1: Linear Voltage Regulator IC 1 Output 200mA SOT-23-5; Manufacturer: Texas Instruments; Output Type: AdjustableProgrammable; Accuracy Percentage: 2%; AEC Qualified: No; Max Supply Voltage: 18V; Dropout Voltage: 160mV; SizeZ_mm: 1.45mm; Output Voltage: 1.24-17.75V; Min Supply Voltage: 2.4V; TJmax_C: +125°C; Nominal Supply Current: 2uA; Number Of Outputs: 1; Standoff Height: 0mm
